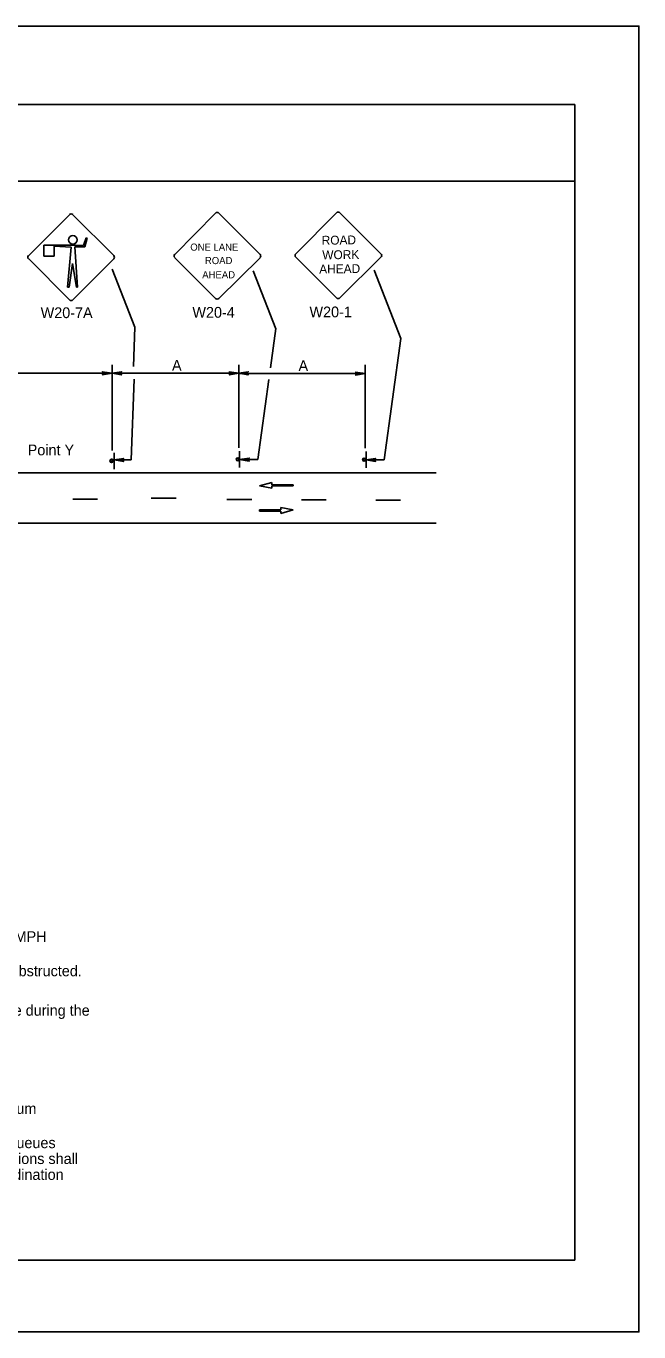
# Model space of a CAD drawing. Extents: x -14145 to -13662, y 30244 to 30661.
# Drawn here: x -13871.13 to -13859.17, y 30451.81 to 30477.31 of the extents above; entities that cross this region are included whole.
import ezdxf

# ---------------------------------------------------------------- set-up
doc = ezdxf.new("R2010")
doc.units = 0
for name, color, linetype in [('1', 7, 'Continuous'), ('10', 7, 'Continuous'), ('2', 7, 'Continuous'), ('61', 7, 'Continuous')]:
    doc.layers.add(name, color=color, linetype=linetype)

msp = doc.modelspace()

# ---------------------------------------------------------------- linework, layer by layer
at = {"layer": '1'}
for p, q in [((-13870.284, 30473.624), (-13871.079, 30472.829)), ((-13869.422, 30472.829), (-13870.217, 30473.624)), ((-13867.435, 30473.653), (-13868.23, 30472.85)), ((-13866.566, 30472.85), (-13867.368, 30473.653)), ((-13865.075, 30473.662), (-13865.87, 30472.859)), ((-13864.206, 30472.859), (-13865.008, 30473.662)), ((-13870.164, 30473.032), (-13870.787, 30473.032)), ((-13870.787, 30473.032), (-13870.787, 30472.814)), ((-13870.014, 30473.024), (-13870.164, 30473.032)), ((-13869.962, 30473.174), (-13870.014, 30473.024)), ((-13869.984, 30472.994), (-13869.939, 30473.167)), ((-13869.939, 30473.167), (-13869.962, 30473.174)), ((-13871.079, 30472.762), (-13870.284, 30471.959)), ((-13870.787, 30472.814), (-13870.584, 30472.814)), ((-13870.584, 30472.814), (-13870.584, 30473.009)), ((-13870.584, 30473.009), (-13870.254, 30472.987)), ((-13870.254, 30472.987), (-13870.322, 30472.207)), ((-13870.217, 30471.959), (-13869.422, 30472.762)), ((-13870.127, 30472.207), (-13870.179, 30472.994)), ((-13870.179, 30472.994), (-13869.984, 30472.994)), ((-13868.23, 30472.784), (-13867.435, 30471.989)), ((-13867.368, 30471.989), (-13866.566, 30472.784)), ((-13865.87, 30472.793), (-13865.075, 30471.998)), ((-13865.008, 30471.998), (-13864.206, 30472.793)), ((-13870.292, 30472.207), (-13870.224, 30472.672)), ((-13870.224, 30472.672), (-13870.149, 30472.207)), ((-13869.01, 30471.427), (-13869.454, 30472.558)), ((-13866.259, 30471.398), (-13866.702, 30472.529)), ((-13863.818, 30471.204), (-13864.342, 30472.538)), ((-13870.322, 30472.207), (-13870.292, 30472.207)), ((-13870.149, 30472.207), (-13870.127, 30472.207)), ((-13869.034, 30470.659), (-13869.01, 30471.427)), ((-13866.364, 30470.635), (-13866.258, 30471.399)), ((-13864.144, 30468.836), (-13863.818, 30471.204)), ((-13869.454, 30470.527), (-13874.338, 30470.527)), ((-13869.454, 30469.016), (-13869.454, 30470.692)), ((-13866.982, 30470.527), (-13869.454, 30470.527)), ((-13866.982, 30469.07), (-13866.982, 30470.692)), ((-13864.516, 30470.521), (-13866.982, 30470.521)), ((-13864.516, 30469.064), (-13864.516, 30470.692)), ((-13869.082, 30468.836), (-13869.021, 30470.414)), ((-13866.61, 30468.842), (-13866.395, 30470.408)), ((-13869.412, 30468.974), (-13869.412, 30468.656)), ((-13866.964, 30469.004), (-13866.964, 30468.686)), ((-13864.498, 30468.998), (-13864.498, 30468.68)), ((-13869.082, 30468.836), (-13869.412, 30468.836)), ((-13866.61, 30468.842), (-13866.964, 30468.842)), ((-13864.144, 30468.836), (-13864.498, 30468.836)), ((-13889.41, 30468.586), (-13863.13, 30468.586)), ((-13866.336, 30468.394), (-13866.577, 30468.328)), ((-13866.577, 30468.328), (-13866.333, 30468.282)), ((-13866.336, 30468.349), (-13866.336, 30468.394)), ((-13865.919, 30468.349), (-13866.336, 30468.349)), ((-13866.333, 30468.282), (-13866.333, 30468.327)), ((-13866.333, 30468.327), (-13865.919, 30468.327)), ((-13865.919, 30468.327), (-13865.919, 30468.349)), ((-13869.736, 30468.07), (-13870.216, 30468.07)), ((-13868.202, 30468.088), (-13868.688, 30468.088)), ((-13866.726, 30468.064), (-13867.212, 30468.064)), ((-13865.274, 30468.058), (-13865.76, 30468.058)), ((-13863.822, 30468.052), (-13864.308, 30468.052)), ((-13866.163, 30467.859), (-13866.577, 30467.859)), ((-13866.577, 30467.859), (-13866.577, 30467.836)), ((-13866.577, 30467.836), (-13866.161, 30467.836)), ((-13865.919, 30467.858), (-13866.163, 30467.904)), ((-13866.163, 30467.904), (-13866.163, 30467.859)), ((-13866.161, 30467.791), (-13865.919, 30467.858)), ((-13866.161, 30467.836), (-13866.161, 30467.791)), ((-13889.41, 30467.602), (-13863.13, 30467.602))]:
    msp.add_line(p, q, dxfattribs=at)
for points in [[(-13869.634, 30470.551), (-13869.628, 30470.539), (-13869.454, 30470.527), (-13869.634, 30470.551), (-13869.646, 30470.557), (-13869.454, 30470.527), (-13869.628, 30470.521), (-13869.634, 30470.509), (-13869.454, 30470.527), (-13869.646, 30470.497), (-13869.634, 30470.509)], [(-13869.28, 30470.503), (-13869.286, 30470.515), (-13869.454, 30470.527), (-13869.28, 30470.503), (-13869.268, 30470.497), (-13869.454, 30470.527), (-13869.286, 30470.533), (-13869.28, 30470.545), (-13869.454, 30470.527), (-13869.268, 30470.557), (-13869.28, 30470.545)], [(-13867.156, 30470.545), (-13867.15, 30470.533), (-13866.982, 30470.527), (-13867.156, 30470.545), (-13867.168, 30470.557), (-13866.982, 30470.527), (-13867.15, 30470.515), (-13867.156, 30470.503), (-13866.982, 30470.527), (-13867.168, 30470.497), (-13867.156, 30470.503)], [(-13866.808, 30470.503), (-13866.814, 30470.515), (-13866.982, 30470.527), (-13866.808, 30470.503), (-13866.796, 30470.497), (-13866.982, 30470.527), (-13866.814, 30470.533), (-13866.808, 30470.545), (-13866.982, 30470.527), (-13866.796, 30470.557), (-13866.808, 30470.545)], [(-13864.69, 30470.539), (-13864.684, 30470.527), (-13864.516, 30470.521), (-13864.69, 30470.539), (-13864.702, 30470.551), (-13864.516, 30470.521), (-13864.684, 30470.509), (-13864.69, 30470.497), (-13864.516, 30470.521), (-13864.702, 30470.491), (-13864.69, 30470.497)], [(-13869.238, 30468.812), (-13869.244, 30468.824), (-13869.412, 30468.836), (-13869.238, 30468.812), (-13869.226, 30468.806), (-13869.412, 30468.836), (-13869.244, 30468.842), (-13869.238, 30468.854), (-13869.412, 30468.836), (-13869.226, 30468.866), (-13869.238, 30468.854)], [(-13866.784, 30468.818), (-13866.79, 30468.83), (-13866.964, 30468.842), (-13866.784, 30468.818), (-13866.778, 30468.812), (-13866.964, 30468.842), (-13866.79, 30468.848), (-13866.784, 30468.86), (-13866.964, 30468.842), (-13866.778, 30468.872), (-13866.784, 30468.86)], [(-13864.318, 30468.812), (-13864.324, 30468.824), (-13864.498, 30468.836), (-13864.318, 30468.812), (-13864.312, 30468.806), (-13864.498, 30468.836), (-13864.324, 30468.842), (-13864.318, 30468.854), (-13864.498, 30468.836), (-13864.312, 30468.866), (-13864.318, 30468.854)]]:
    msp.add_lwpolyline(points, dxfattribs=at)
for centre, radius in [((-13870.217, 30473.132), 0.0844), ((-13869.462, 30468.816), 0.0325), ((-13867, 30468.847), 0.0298), ((-13864.534, 30468.841), 0.0298)]:
    msp.add_circle(centre, radius, dxfattribs=at)
for centre, radius, start, end in [((-13870.252, 30473.592), 0.0465, 45, 135), ((-13867.402, 30473.621), 0.0465, 45, 135), ((-13865.042, 30473.63), 0.0465, 45, 135), ((-13871.051, 30472.793), 0.0465, 135, 225), ((-13869.453, 30472.793), 0.0465, 315, 45), ((-13868.197, 30472.818), 0.0465, 135, 225), ((-13866.599, 30472.818), 0.0465, 315, 45), ((-13865.837, 30472.827), 0.0465, 135, 225), ((-13864.239, 30472.827), 0.0465, 315, 45), ((-13865.042, 30472.032), 0.0465, 225, 315), ((-13870.252, 30471.994), 0.0465, 225, 315), ((-13867.402, 30472.023), 0.0465, 225, 315), ((-13869.462, 30468.827), 0.0214, 355.7499, 350.479), ((-13866.999, 30468.847), 0.0214, 355.7499, 350.479), ((-13864.533, 30468.841), 0.0214, 355.7499, 350.479)]:
    msp.add_arc(centre, radius, start, end, dxfattribs=at)
at = {"layer": '10'}
for p, q in [((-13891.874, 30475.777), (-13860.422, 30475.777)), ((-13860.422, 30475.777), (-13860.422, 30453.207)), ((-13891.874, 30474.277), (-13860.422, 30474.277)), ((-13860.422, 30453.207), (-13891.874, 30453.207))]:
    msp.add_line(p, q, dxfattribs=at)
at = {"layer": '61'}
msp.add_lwpolyline([(-13892.174, 30477.307), (-13859.174, 30477.307), (-13859.174, 30451.807), (-13892.174, 30451.807)], close=True, dxfattribs=at)

# ---------------------------------------------------------------- texts
at = {"layer": '1'}
for s, height, p in [('ONE LANE', 0.1386, (-13867.927, 30472.922)), ('ROAD', 0.1389, (-13867.642, 30472.659)), ('AHEAD', 0.139, (-13867.694, 30472.382))]:
    msp.add_text(s, height=height, dxfattribs=at).set_placement(p)
for s, height, rotation, p in [('ROAD', 0.1735, 0.7566, (-13865.362, 30473.037)), ('WORK', 0.1733, 0.7588, (-13865.35, 30472.752)), ('AHEAD', 0.1735, 0.7481, (-13865.41, 30472.475))]:
    msp.add_text(s, height=height, rotation=rotation, dxfattribs=at).set_placement(p)
at = {"layer": '2'}
for s, p in [('W20-7A', (-13870.847, 30471.605)), ('W20-4', (-13867.886, 30471.612)), ('W20-1', (-13865.601, 30471.62)), ('A', (-13868.284, 30470.578)), ('A', (-13865.815, 30470.572)), ('Point Y', (-13871.1, 30468.925)), ('    a. The operation moves intermittently or continuously at an average speed of less than 1 MPH', (-13882.72, 30459.421)), ('    b. Sight distance between the flagger and any vehicle between Points X and Y will be unobstructed.', (-13882.72, 30458.752)), ('    d. The ADT is not greater than approximately 1500, or the average 5-minute traffic volume during the', (-13882.72, 30457.981)), ('    b. The W20-7A Sign may be eliminated if the flagger is clearly visible to traffic for a minimum ', (-13882.714, 30456.064)), ('4.  When a highway-rail grade crossing exists within the work zone, or it is anticipated that queues ', (-13882.714, 30455.395)), ('    resulting from the lane closure might extend through a highway-rail grade crossing, provisions shall ', (-13882.714, 30455.085)), ('    be made to eliminate conflicts, which may require placing a flagger at the crossing.  Coordination ', (-13882.714, 30454.775))]:
    msp.add_text(s, height=0.21, dxfattribs=at).set_placement(p)

doc.saveas('drawing.dxf')
